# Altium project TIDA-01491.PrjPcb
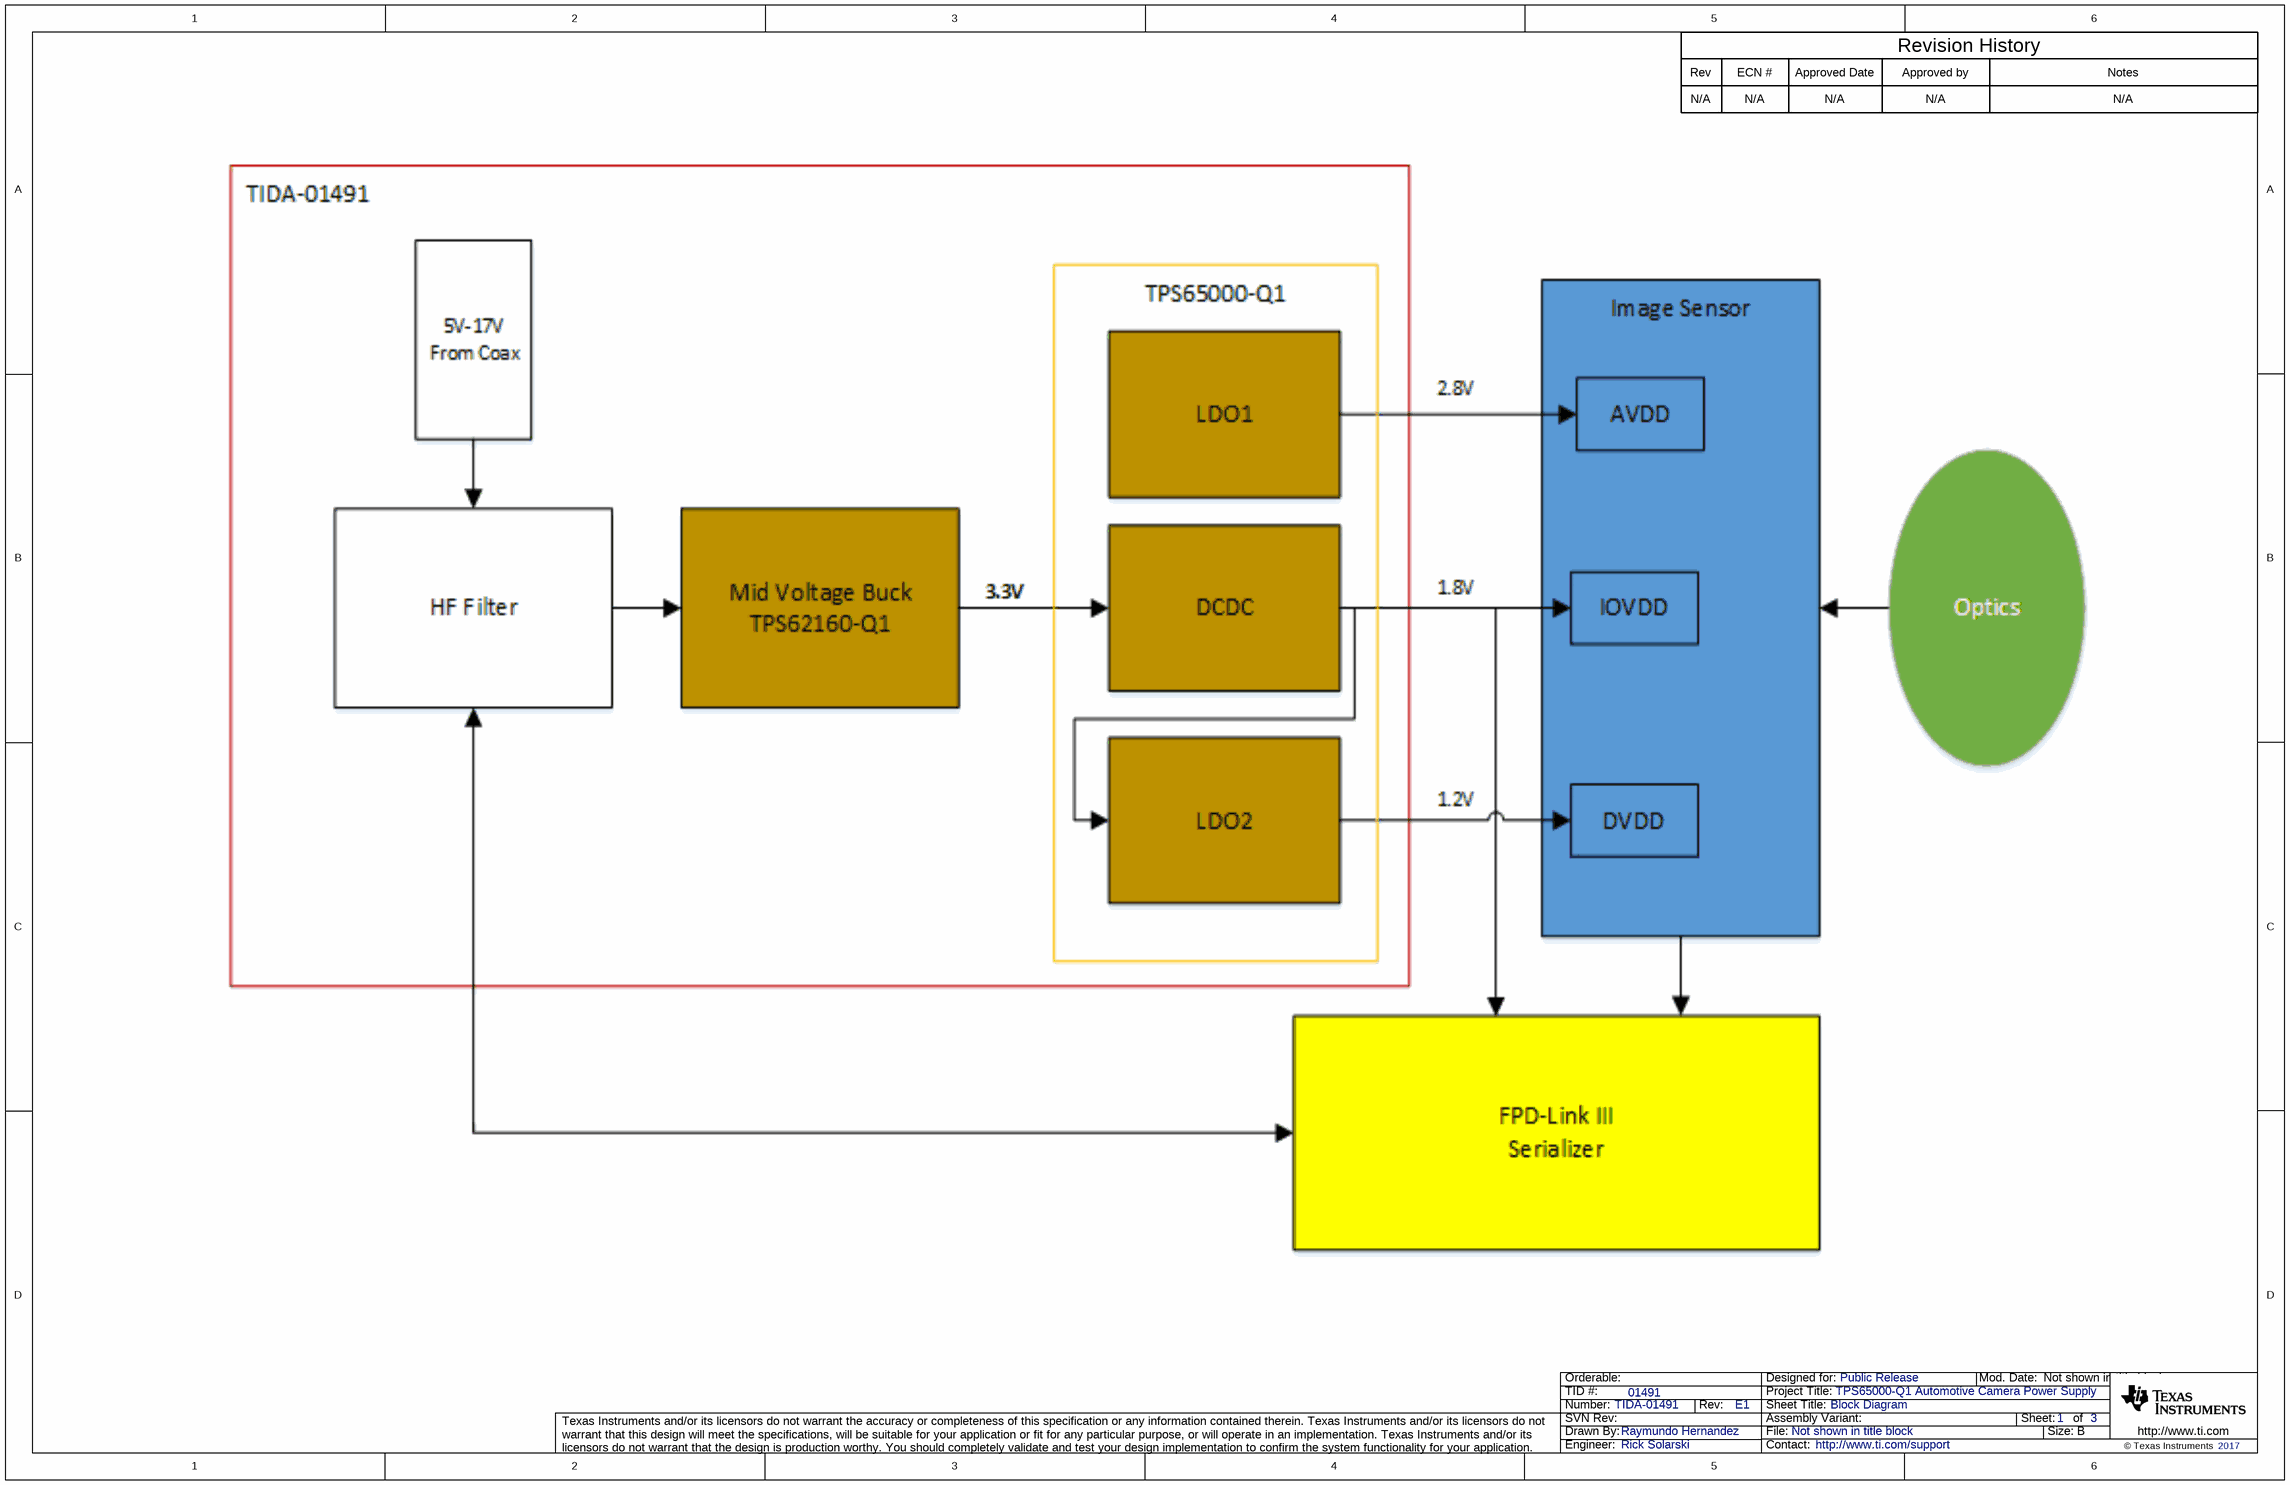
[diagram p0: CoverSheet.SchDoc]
CopyrightYear: 2017; PCB_Layout: Gordon Varney; PCB_Rev: 001; PRJ_Customer: Public Release; PRJ_Engineer: Rick Solarski; PRJ_Number: TIDA-01491; PRJ_Title: TPS65000-Q1 Automotive Camera Power Supply; SCH_Rev: E1; TechSupport: http://www.ti.com/support; TID: 01491
3 sheets, 73 parts. Net scope: global (net labels, ports and power ports of the same name join across sheets).
Board file: TIDA-01491.PcbDoc
Sheets:
  CoverSheet.SchDoc
  TIDA-01491.SchDoc
  EVM_Hardware.SchDoc

## Sheet CoverSheet.SchDoc: Block Diagram
size 431 x 279 mm; Date: Not shown in title block; ApprovedBy: Not shown in title block; CheckedBy: Not shown in title block; Author: Not shown in title block; CompanyName: Not shown in title block; DrawnBy: Raymundo Hernandez; Engineer: Not shown in title block; Organization: Not shown in title block; Address1: Not shown in title block; Address2: Not shown in title block; Address3: Not shown in title block; Address4: Not shown in title block; DocumentNumber: 1; Revision: Use project parameter SCH_Rev; SheetNumber: 1; SheetTotal: 3; PageSetup: Record=PageOptions¦CenterHorizontal=True¦CenterVertical=True¦PrintScale=1.00¦XCorrection=1.00¦YCorrection=1.00¦PrintKind=0¦BorderSize=5000000¦LeftOffset=0¦BottomOffset=0¦Orientation=2¦PaperLength=1000¦PaperWidth=1000¦Scale=100¦PaperSource=15¦PrintQuality=600¦MediaType=1¦DitherType=10¦PaperKind=Letter¦PrintScaleMode=1

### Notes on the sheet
- Rev
- N/A
- ECN #
- Approved Date
- Approved by
- Revision History
- Notes

## Sheet TIDA-01491.SchDoc: Schematic Automotive Camera Power Supply
size 431 x 279 mm; Date: Not shown in title block; ApprovedBy: Not shown in title block; CheckedBy: Not shown in title block; Author: Not shown in title block; CompanyName: Not shown in title block; DrawnBy: Rick Solarski; Engineer: Not shown in title block; Organization: Not shown in title block; Address1: Not shown in title block; Address2: Not shown in title block; Address3: Not shown in title block; Address4: Not shown in title block; DocumentNumber: 1; Revision: Use project parameter SCH_Rev; SheetNumber: 2; SheetTotal: 3; PageSetup: Record=PageOptions¦CenterHorizontal=True¦CenterVertical=True¦PrintScale=0.62¦XCorrection=1.00¦YCorrection=1.00¦PrintKind=0¦BorderSize=5000000¦LeftOffset=0¦BottomOffset=0¦Orientation=2¦PaperLength=1000¦PaperWidth=1000¦Scale=100¦PaperSource=15¦PrintQuality=-3¦MediaType=1¦DitherType=10¦PrintScaleMode=1¦PaperKind=Letter¦PaperIndex=1
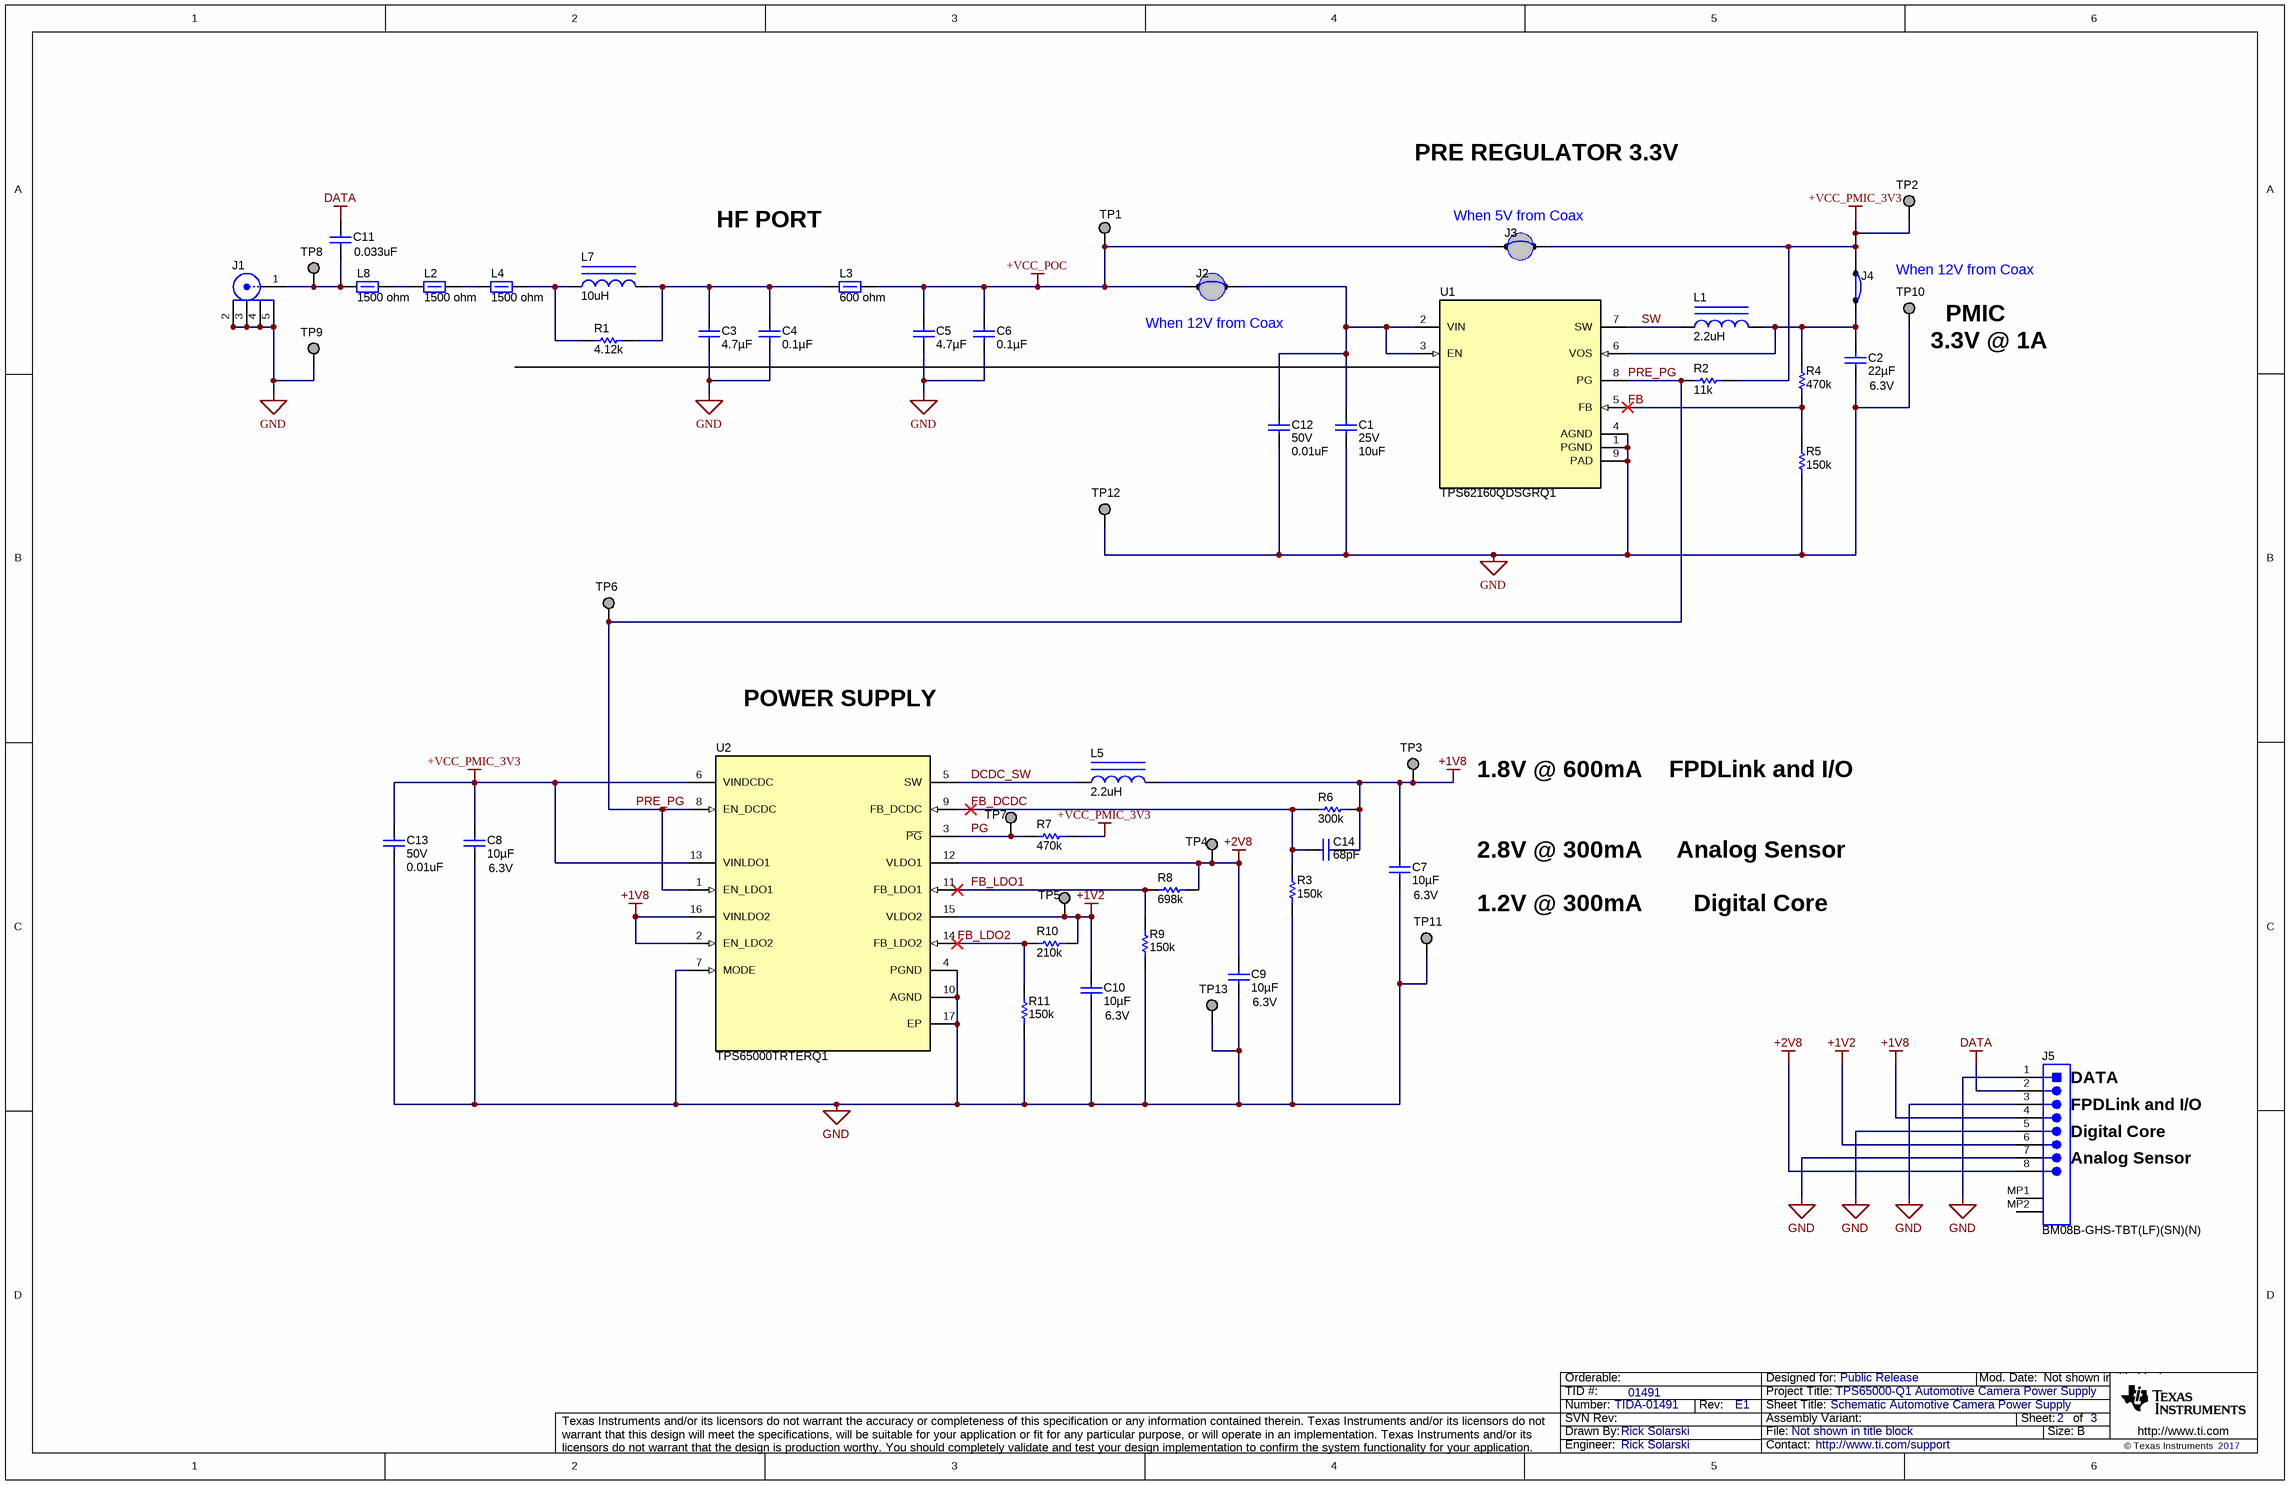
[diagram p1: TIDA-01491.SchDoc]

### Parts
C1  VDC_V: 25V  ValueDisplayed: 10uF  [1206_190L]  (hidden comment: GCM31CC71E106KA03L)
C2  ValueDisplayed: 22µF  Value2: 6.3V  [1206_180L]  (hidden comment: GCM31CR70J226KE23L)
C3  ValueDisplayed: 4.7µF  [0805L]  (hidden comment: GCM21BC71E475KE36L)
C4  ValueDisplayed: 0.1µF  [0603L]  (hidden comment: CGA3E2X7R1E104K080AA)
C5  ValueDisplayed: 4.7µF  [0805L]  (hidden comment: GCM21BC71E475KE36L)
C6  ValueDisplayed: 0.1µF  [0603L]  (hidden comment: CGA3E2X7R1E104K080AA)
C7  ValueDisplayed: 10µF  Value2: 6.3V  [0805L]  (hidden comment: GCM21BR70J106KE22L)
C8  ValueDisplayed: 10µF  Value2: 6.3V  [0805L]  (hidden comment: GCM21BR70J106KE22L)
C9  ValueDisplayed: 10µF  Value2: 6.3V  [0805L]  (hidden comment: GCM21BR70J106KE22L)
C10  ValueDisplayed: 10µF  Value2: 6.3V  [0805L]  (hidden comment: GCM21BR70J106KE22L)
C11  ValueDisplayed: 0.033uF  [0402L]  (hidden comment: CGA2B1X7R1E333K050BC)
C12  VDC_V: 50V  ValueDisplayed: 0.01uF  [0402]  (hidden comment: CGA2B3X7R1H103K050BB)
C13  VDC_V: 50V  ValueDisplayed: 0.01uF  [0402]  (hidden comment: CGA2B3X7R1H103K050BB)
C14  ValueDisplayed: 68pF  [0603L]  (hidden comment: GCM1885C1H680JA16D)
J1  59S10H-40ML5-Z  [Rosenberger_59S10H-40ML5-Z]  (value not drawn)
J2  JMP-36-30X40SMT  [JMP-36-30X40SMT]  (value not drawn)
J3  JMP-36-30X40SMT  [JMP-36-30X40SMT]  (value not drawn)
J4  JMP-36-30X40SMT  [JMP-36-30X40SMT]  (value not drawn)
J5  BM08B-GHS-TBT(LF)(SN)(N)  [JST_BM08B-GHS-TBT]
L1  ValueDisplayed: 2.2uH  [SRN2010TA]  (hidden comment: SRN2010TA-2R2M)
L2  ValueDisplayed: 1500 ohm  [0603L]  (hidden comment: BLM18HE152SN1D)
L3  ValueDisplayed: 600 ohm  [0603L]  (hidden comment: BLM18KG601SN1D)
L4  ValueDisplayed: 1500 ohm  [0603L]  (hidden comment: BLM18HE152SN1D)
L5  ValueDisplayed: 2.2uH  [SRN2010TA]  (hidden comment: SRN2010TA-2R2M)
L7  ValueDisplayed: 10uH  [LQH3NPZ_JR]  (hidden comment: LQH3NPZ100MJRL)
L8  ValueDisplayed: 1500 ohm  [0603L]  (hidden comment: BLM18HE152SN1D)
R1  ValueDisplayed: 4.12k  [0603]  (hidden comment: ERA-3AEB4121V)
R2  ValueDisplayed: 11k  [0402L]  (hidden comment: CRCW040211K0JNED)
R3  ValueDisplayed: 150k  [0402L]  (hidden comment: ERJ-2RKF1503X)
R4  ValueDisplayed: 470k  [0402L]  (hidden comment: ERJ-2RKF4703X)
R5  ValueDisplayed: 150k  [0402L]  (hidden comment: ERJ-2RKF1503X)
R6  ValueDisplayed: 300k  [0402L]  (hidden comment: CRCW0402300KFKED)
R7  ValueDisplayed: 470k  [0402L]  (hidden comment: ERJ-2RKF4703X)
R8  ValueDisplayed: 698k  [0402L]  (hidden comment: ERJ-2RKF6983X)
R9  ValueDisplayed: 150k  [0402L]  (hidden comment: ERJ-2RKF1503X)
R10  ValueDisplayed: 210k  [0402L]  (hidden comment: ERJ-2RKF2103X)
R11  ValueDisplayed: 150k  [0402L]  (hidden comment: ERJ-2RKF1503X)
TP1  TP_SM_1MM  [TP_SM_1MM]  (value not drawn)  (no BOM)
TP2  TP_SM_1MM  [TP_SM_1MM]  (value not drawn)  (no BOM)
TP3  TP_SM_1MM  [TP_SM_1MM]  (value not drawn)  (no BOM)
TP4  TP_SM_1MM  [TP_SM_1MM]  (value not drawn)  (no BOM)
TP5  TP_SM_1MM  [TP_SM_1MM]  (value not drawn)  (no BOM)
TP6  TP_SM_1MM  [TP_SM_1MM]  (value not drawn)  (no BOM)
TP7  TP_SM_1MM  [TP_SM_1MM]  (value not drawn)  (no BOM)
TP8  TP_SM_1MM  [TP_SM_1MM]  (value not drawn)  (no BOM)
TP9  TP_SM_1MM  [TP_SM_1MM]  (value not drawn)  (no BOM)
TP10  TP_SM_1MM  [TP_SM_1MM]  (value not drawn)  (no BOM)
TP11  TP_SM_1MM  [TP_SM_1MM]  (value not drawn)  (no BOM)
TP12  TP_SM_1MM  [TP_SM_1MM]  (value not drawn)  (no BOM)
TP13  TP_SM_1MM  [TP_SM_1MM]  (value not drawn)  (no BOM)
U1  TPS62160QDSGRQ1  [DSG0008A]
U2  TPS65000TRTERQ1  [RTE0016C]

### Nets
+1V2: C10.1 J5.6 R10.2 TP5.1 U2.15(VLDO2)
+1V8: C7.1 C14.1 J5.4 L5.2 R6.2 TP3.1 U2.2(EN_LDO2) U2.16(VINLDO2)
+2V8: C9.1 J5.8 R8.2 TP4.1 U2.12(VLDO1)
+VCC_PMIC_3V3: C8.1 C13.1 J3.2 J4.1 R2.2 R7.2 TP2.1 U2.6(VINDCDC) U2.13(VINLDO1)
+VCC_POC: C5.1 C6.1 J2.1 J3.1 L3.2 TP1.1
DATA: C11.1 J5.2
GND: C1.2 C2.2 C3.2 C4.2 C5.2 C6.2 C7.2 C8.2 C9.2 C10.2 C12.2 C13.2 J1.2 J1.3 J1.4 J1.5 J5.1 J5.3 J5.5 J5.7 R3.1 R5.1 R9.1 R11.1 TP9.1 TP10.1 TP11.1 TP12.1 TP13.1 U1.1(PGND) U1.4(AGND) U1.9(PAD) U2.4(PGND) U2.7(MODE) U2.10(AGND) U2.17(EP)
DCDC_SW: L5.1 U2.5(SW)
FB: R4.1 R5.2 U1.5(FB)
FB_DCDC: C14.2 R3.2 R6.1 U2.9(FB_DCDC)
FB_LDO1: R8.1 R9.2 U2.11(FB_LDO1)
FB_LDO2: R10.1 R11.2 U2.14(FB_LDO2)
PG: R7.1 TP7.1 U2.3(~{PG})
PRE_PG: R2.1 TP6.1 U1.8(PG) U2.1(EN_LDO1) U2.8(EN_DCDC)
SW: L1.1 U1.7(SW)
NetC1_1: C1.1 C12.1 J2.2 U1.2(VIN) U1.3(EN)
NetC2_1: C2.1 J4.2 L1.2 R4.2 U1.6(VOS)
NetC3_1: C3.1 C4.1 L3.1 L7.2 R1.2
NetC11_2: C11.2 J1.1 L8.1 TP8.1
NetL2_1: L2.1 L8.2
NetL2_2: L2.2 L4.1
NetL4_2: L4.2 L7.1 R1.1

Not connected (* = marked no-connect by the designer): J5 MP1 MP2

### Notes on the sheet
- PRE REGULATOR 3.3V
- HF PORT
- (near J3) When 5V from Coax
- (near J2) When 12V from Coax
- (near TP10) When 12V from Coax
- (near TP10) PMIC
- (near TP10) 3.3V @ 1A
- POWER SUPPLY
- 1.8V @ 600mA
- FPDLink and I/O
- 2.8V @ 300mA
- 1.2V @ 300mA
- Analog Sensor
- Digital Core
- (near J5) FPDLink and I/O
- (near J5) DATA
- (near J5) Analog Sensor
- (near J5) Digital Core

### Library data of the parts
C1 = CMP-0008807-2: CAP, CERM, 10 uF, 25 V, +/- 10%, X7S, AEC-Q200 Grade 1, 1206_190; Manufacturer: MuRata; TaMin_C: -55°C; Polarized: N; SizeAreaWB_mm2: 10.92; Value1: Unknown; U/M: EA; Value: 10uF; TaMax_C: 125°C; SizeZ_mm: 1.9; SizeX_mm: 3.2; SizeY_mm: 1.6; Cap_Case: 1206; SizeArea_mm2: 5.12; CompType: Capacitor; AEC Qualified: Y; Cap_F: 10µF; AEC Grade: 1; AEC Category: Q200
C2 = GCM31CR70J226KE23L: CAP, CERM, 22 µF, 6.3 V,+/- 10%, X7R, AEC-Q200 Grade 1, 1206; Manufacturer: MuRata; Polarized: N; CompType: Capacitor; Value: 22uF; U/M: EA; Cap_F: 0.000022; Tolerance_%: 10; VDC_V: 6.3; TaMin_C: -55; TaMax_C: 125; Cap_Case: 1206; SizeArea_mm2: 5.12; SizeAreaWB_mm2: 10.92; SizeX_mm: 3.2; SizeY_mm: 1.6; SizeZ_mm: 1.8; AEC Category: Q200; AEC Qualified: Y; AEC Grade: 1
C3 C5 = GCM21BC71E475KE36L: CAP, CERM, 4.7 µF, 25 V,+/- 10%, X7S, AEC-Q200 Grade 1, 0805; Manufacturer: MuRata; Value: 4.7uF; VDC_V: 25; Tolerance_%: 10; Polarized: N; CompType: Capacitor; U/M: EA; Cap_F: 0.0000047; Value2: 25V; TaMin_C: -55; TaMax_C: 125; Cap_Case: 0805; SizeArea_mm2: 2.5; SizeAreaWB_mm2: 6.75; SizeX_mm: 2; SizeY_mm: 1.25; SizeZ_mm: 1.45; AEC Category: Q200; AEC Qualified: Y; AEC Grade: 1
C4 C6 = CGA3E2X7R1E104K080AA: CAP, CERM, 0.1 µF, 25 V,+/- 10%, X7R, AEC-Q200 Grade 1, 0603; Manufacturer: TDK; Value: 0.1uF; VDC_V: 25; Tolerance_%: 10; Polarized: N; CompType: Capacitor; U/M: EA; Cap_F: 0.0000001; Value2: 25V; TaMin_C: -55; TaMax_C: 125; Cap_Case: 0603; SizeArea_mm2: 1.28; SizeAreaWB_mm2: 4.68; SizeX_mm: 1.6; SizeY_mm: 0.8; SizeZ_mm: 1; AEC Category: Q200; AEC Qualified: Y
C7-C10 = GCM21BR70J106KE22L: CAP, CERM, 10 µF, 6.3 V,+/- 10%, X7R, AEC-Q200 Grade 1, 0805; Manufacturer: MuRata; Polarized: N; CompType: Capacitor; Value: 10uF; U/M: EA; Cap_F: 0.00001; Tolerance_%: 10; VDC_V: 6.3; TaMin_C: -55; TaMax_C: 125; Cap_Case: 0805; SizeArea_mm2: 2.5; SizeAreaWB_mm2: 6.75; SizeX_mm: 2; SizeY_mm: 1.25; SizeZ_mm: 1.45; AEC Category: Q200; AEC Qualified: Y; AEC Grade: 1; Green_Lifecycle: Active; Green_REACh: Passed
C11 = CMP-0006306-2: CAP, CERM, 0.033 uF, 25 V, +/- 10%, X7R, AEC-Q200 Grade 1, 0402; Manufacturer: TDK; TaMin_C: -55°C; Polarized: N; SizeAreaWB_mm2: 3; Value1: Unknown; U/M: EA; TaMax_C: 125°C; SizeZ_mm: 0.6; SizeX_mm: 1; SizeY_mm: 0.5; Cap_Case: 0402; Value2: 25V; CompType: Capacitor; AEC Qualified: Y; Cap_F: 33nF; AEC Category: Q200
C12 C13 = CMP-0006324-2: CAP, CERM, 0.01 uF, 50 V, +/- 10%, X7R, AEC-Q200 Grade 1, 0402; Manufacturer: TDK; TaMin_C: -55°C; ESR_ohm: 3.33065d; Polarized: N; SizeAreaWB_mm2: 3; Value1: 0.333065 ohm; U/M: EA; Value: 0.01uF; TaMax_C: 125°C; SizeZ_mm: 0.6; SizeX_mm: 1; SizeY_mm: 0.5; AEC Qualified: Y; Cap_F: 10nF; IRMS_A: 3.23373dA; AEC Category: Q200
C14 = CMP-0007129-4: CAP, CERM, 68 pF, 50 V, +/- 5%, C0G/NP0, AEC-Q200 Grade 1, 0603; Manufacturer: MuRata; TaMin_C: -55°C; Polarized: N; SizeAreaWB_mm2: 4.68; Value1: Unknown; U/M: EA; Value: 68pF; TaMax_C: 125°C; SizeZ_mm: 1; SizeX_mm: 1.6; SizeY_mm: 0.8; Cap_Case: 0603; Value2: 50V; SizeArea_mm2: 1.28; CompType: Capacitor; AEC Qualified: Y; AEC Category: Q200
J1 = CMP-0075127-1: Connector, HF, 50 Ohm, TH; Manufacturer: Rosenberger; CNHeader: False; Green_Lifecycle: Not Set; Gender: Male; Green_REACh: Incomplete; ContactFinish: Gold
J2-J4 = CMP-0003883-1: Jumper, SMT; Manufacturer: Any
J5 = CMP-0078455-1: Header(shrouded), 1.25mm, 8x1, Tin, TH; Manufacturer: JST Manufacturing; Pitch_mm: 1.25; Gender: Male; Cert_UL: Y; Voltage_V: 50V; Current_A: 1A; Row_Count: 1
L1 L5 = CMP-0056730-1: Inductor, Shielded, Ferrite, 2.2 uH, 1.2 A, 0.174 ohm, AEC-Q200 Grade 1, SMD; Manufacturer: Bourns; Isat: 1.26A @ 30% inductance drop; Irms: 1.2A @ 40C rise; Green_Lifecycle: Active; SizeAreaWB_mm2: 7.8; DCR_ohm: 1.74d; Green_REACh: Passed; Value: 2.2uH; Imax_A: 1.2A; SizeZ_mm: 1; SizeX_mm: 2; SizeY_mm: 1.6; SizeArea_mm2: 3.2; Ind_H: 2.2µH; AEC Qualified: Y; AEC Category: Q200
L2 L4 L8 = BLM18HE152SN1D: Ferrite Bead, 1500 ohm @ 100 MHz, 0.5 A, 0603; Manufacturer: MuRata; Imax_A: 0.5; Value1: 0.5 ohm; Value2: 0.5A; SizeAreaWB_mm2: 4.68; SizeArea_mm2: 1.28; SizeX_mm: 1.6; SizeY_mm: 0.8; SizeZ_mm: 1; ZTyp@100MHz_Ohm: 1500; Green_Lifecycle: Active; Green_REACh: Passed
L3 = BLM18KG601SN1D: Ferrite Bead, 600 ohm @ 100 MHz, 1.3 A, 0603; Manufacturer: MuRata; Value: 600 ohm; Imax_A: 1.3; DCR_ohm: 0.15; Value1: 0.15 ohm; Value2: 1.3A; SizeAreaWB_mm2: 4.68; SizeArea_mm2: 1.28; SizeX_mm: 1.6; SizeY_mm: 0.8; SizeZ_mm: 1; ZTyp@100MHz_Ohm: 600; Green_Lifecycle: Active; Green_REACh: Passed
L7 = CMP-0058702-1: Inductor, Wirewound, Ferrite, 10 uH, 0.81 A, 0.288 ohm, AEC-Q200 Grade 1, SMD; Manufacturer: MuRata; Isat: 0.81A @ 30% inductance drop; Irms: 1.2A @ 40C rise; SizeAreaWB_mm2: 16; DCR_ohm: 2.88d; Value: 10uH; Imax_A: 8.1dA; SizeZ_mm: 1.2; SizeX_mm: 3; Value2: 0.81A; SizeArea_mm2: 9; Ind_H: 10µH; AEC Qualified: Y; AEC Grade: 1; AEC Category: Q200
R1 = CMP-0023378-3: RES, 4.12 k, 0.1%, 0.1 W, AEC-Q200 Grade 0, 0603; Manufacturer: Panasonic; Power_W: 100mW; TempCo: 25 ppm/C; Value_Code: 4k12; U/M: EA; Value: 4.12k; EIA_Code: E192; SizeX_mm: 1.6; SizeY_mm: 0.8; SizeZ_mm: 1; Value2: 0.1W; SizeArea_mm2: 1.28; AEC Qualified: Y; VDC_V: 75V; AEC Grade: 0; AEC Category: Q200
R2 = CMP-0026830-3: RES, 11 k, 5%, 0.063 W, AEC-Q200 Grade 0, 0402; Manufacturer: Vishay-Dale; Power_W: 63mW; TempCo: 200 ppm/C; Value_Code: 11k0; Value: 11k; EIA_Code: E24; SizeX_mm: 1; SizeY_mm: 0.5; SizeZ_mm: 0.6; Value2: 0.063W; CompType: Resistor; AEC Qualified: Y; VDC_V: 50V; AEC Grade: 0; AEC Category: Q200
R3 R5 R11 = CMP-0026669-1: RES, 150 k, 1%, 0.1 W, AEC-Q200 Grade 0, 0402; Manufacturer: Panasonic; Power_W: 100mW; TempCo: 100 ppm/C; U/M: EA; Value: 150k; EIA_Code: E96; SizeX_mm: 1; SizeY_mm: 0.5; SizeZ_mm: 0.6; Value2: 0.1W; CompType: Resistor; AEC Qualified: Y; VDC_V: 50V; AEC Grade: 0; AEC Category: Q200
R4 R7 = CMP-0078374-1: RES, 470 k, 1%, .1 W, AEC-Q200 Grade 0, 0402; Manufacturer: Panasonic; CompType: Resistor; Value: 470k; Res_ohm: 470000; Tolerance_%: 1; Power_W: 0.1; Value2: .1W; VDC_V: 50; TempCo: 100 ppm/C; SizeArea_mm2: 0.5; SizeZ_mm: 0.6; AEC Category: Q200; AEC Qualified: Y; AEC Grade: 0
R6 = CRCW0402300KFKED: RES, 300 k, 1%, 0.063 W, AEC-Q200 Grade 0, 0402; Manufacturer: Vishay-Dale; CompType: Resistor; Value: 300k; Res_ohm: 300000; Tolerance_%: 1; Power_W: 0.063; Value2: 0.063W; VDC_V: 50; TempCo: 100 ppm/C; SizeArea_mm2: 0.5; SizeZ_mm: 0.6; U/M: EA; AEC Category: Q200; AEC Qualified: Y; AEC Grade: 0
R8 = CMP-0078375-1: RES, 698 k, 1%, .1 W, AEC-Q200 Grade 0, 0402; Manufacturer: Panasonic; CompType: Resistor; Value: 698k; Res_ohm: 698000; Tolerance_%: 1; Power_W: 0.1; Value2: .1W; VDC_V: 50; TempCo: 100 ppm/C; SizeArea_mm2: 0.5; SizeZ_mm: 0.6; EIA_Code: E96; AEC Category: Q200; AEC Qualified: Y; AEC Grade: 0
R9 = CMP-0026669-1: RES, 150 k, 1%, 0.1 W, AEC-Q200 Grade 0, 0402; Manufacturer: Panasonic; Power_W: 100mW; TempCo: 100 ppm/C; U/M: EA; Value: 150k; EIA_Code: E96; SizeX_mm: 1; SizeY_mm: 0.5; SizeZ_mm: 0.6; Value2: 0.1W; AEC Qualified: Y; VDC_V: 50V; AEC Grade: 0; AEC Category: Q200
R10 = CMP-0026678-1: RES, 210 k, 1%, 0.1 W, AEC-Q200 Grade 0, 0402; Manufacturer: Panasonic; Power_W: 100mW; TempCo: 100 ppm/C; U/M: EA; Value: 210k; EIA_Code: E96; SizeX_mm: 1; SizeY_mm: 0.5; SizeZ_mm: 0.6; Value2: 0.1W; CompType: Resistor; AEC Qualified: Y; VDC_V: 50V; AEC Grade: 0; AEC Category: Q200
TP1-TP13 = CMP-0003825-1: 1mm Test Point, SMT; Manufacturer: Any
U1 = TPS62160QDSGRQ1: 3V-17V 1A Automotive Step-Down Converters in 2x2SON, DSG0008A (WSON-8); Alternate PartNumber: TPS62160QDSGTQ1; Manufacturer: Texas Instruments; SymbolCreator: Altium; SizeArea_mm2: 4; SizeAreaWB_mm2: 9; SizeX_mm: 2; SizeZ_mm: 0.8; CompType: IC; U/M: EA
U2 = TPS65000TRTERQ1: 2.25MHz Step-Down Converter with Dual LDOs & SVS Power Management IC (PMIC), RTE0016C (WQFN-16); Manufacturer: Texas Instruments; SymbolCreator: Altium; SizeArea_mm2: 9; SizeAreaWB_mm2: 16; SizeX_mm: 3; SizeZ_mm: 0.8; U/M: EA

## Sheet EVM_Hardware.SchDoc: Hardware
size 431 x 279 mm; Date: Not shown in title block; ApprovedBy: Not shown in title block; CheckedBy: Not shown in title block; Author: Not shown in title block; CompanyName: Not shown in title block; DrawnBy: Gordon Varney; Engineer: Not shown in title block; Organization: Not shown in title block; Address1: Not shown in title block; Address2: Not shown in title block; Address3: Not shown in title block; Address4: Not shown in title block; DocumentNumber: 1; Revision: Use project parameter SCH_Rev; SheetNumber: 3; SheetTotal: 3; PageSetup: Record=PageOptions¦CenterHorizontal=True¦CenterVertical=True¦PrintScale=1.00¦XCorrection=1.00¦YCorrection=1.00¦PrintKind=0¦BorderSize=5000000¦LeftOffset=0¦BottomOffset=0¦Orientation=2¦PaperLength=1000¦PaperWidth=1000¦Scale=100¦PaperSource=15¦PrintQuality=600¦MediaType=1¦DitherType=10¦PaperKind=Letter¦PrintScaleMode=1
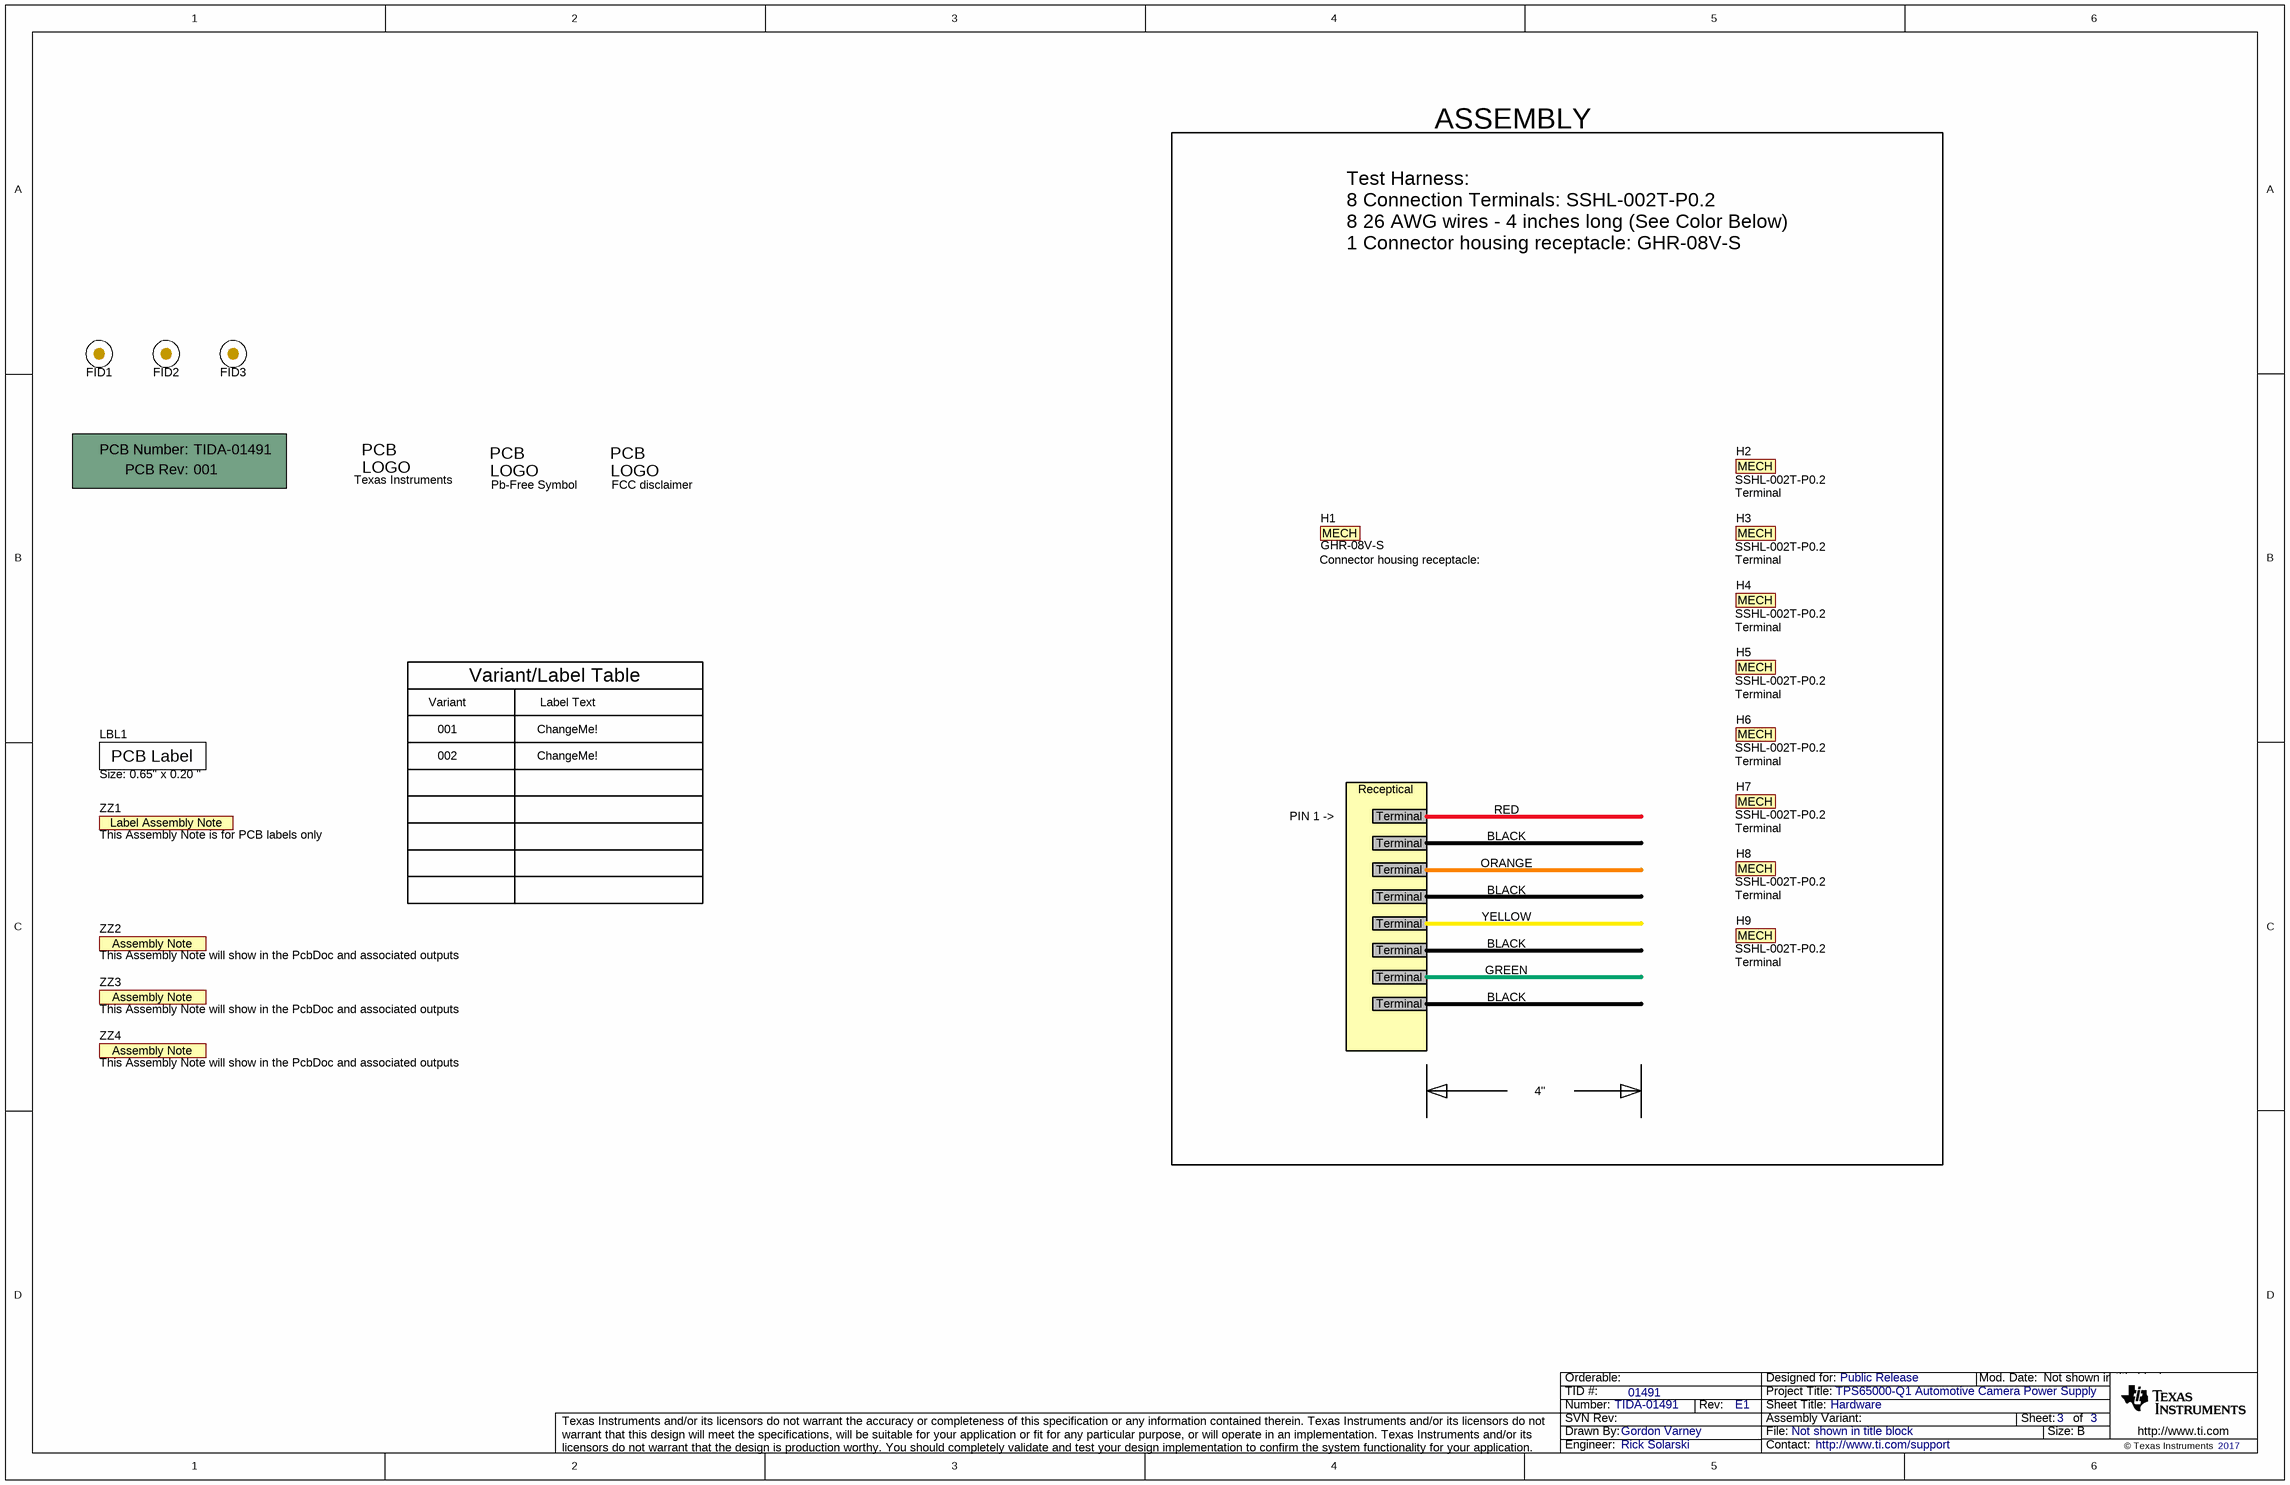
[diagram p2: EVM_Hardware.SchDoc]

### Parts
!PCB1  Printed Circuit Board  (value not drawn)  (mechanical)
FID1  Fiducial  [Fiducial6.4-20]  (value not drawn)  (no BOM)
FID2  Fiducial  [Fiducial6.4-20]  (value not drawn)
FID3  Fiducial  [Fiducial6.4-20]  (value not drawn)
H1  GHR-08V-S  CompType: Connector housing receptacle:  (mechanical)
H2  SSHL-002T-P0.2  PackageReference: Terminal  (mechanical)
H3  SSHL-002T-P0.2  PackageReference: Terminal  (mechanical)
H4  SSHL-002T-P0.2  PackageReference: Terminal  (mechanical)
H5  SSHL-002T-P0.2  PackageReference: Terminal  (mechanical)
H6  SSHL-002T-P0.2  PackageReference: Terminal  (mechanical)
H7  SSHL-002T-P0.2  PackageReference: Terminal  (mechanical)
H8  SSHL-002T-P0.2  PackageReference: Terminal  (mechanical)
H9  SSHL-002T-P0.2  PackageReference: Terminal  (mechanical)
LBL1  Size: 0.65" x 0.20 "  [Label_650x200]
Logo1  Pb-Free Symbol  [Pb-Free_Overlay_Small]  (no BOM)
Logo2  FCC disclaimer  [FCC_disclaimer_stacked]  (no BOM)
Logo3  Texas Instruments  [TI_Symbol_Overlay_Small]  (no BOM)
ZZ1  This Assembly Note is for PCB labels only  [AssemblyNoteLabel]  (no BOM)
ZZ2  This Assembly Note will show in the PcbDoc and associated outputs  [AssemblyNote]  (no BOM)
ZZ3  This Assembly Note will show in the PcbDoc and associated outputs  [AssemblyNote]  (no BOM)
ZZ4  This Assembly Note will show in the PcbDoc and associated outputs  [AssemblyNote]  (no BOM)

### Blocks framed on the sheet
ASSEMBLY: H1-H9

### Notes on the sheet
- Test Harness:
  8 Connection Terminals: SSHL-002T-P0.2
  8 26 AWG wires - 4 inches long (See Color Below)
  1 Connector housing receptacle: GHR-08V-S
- Variant
- Variant/Label Table
- Label Text
- 001
- 002
- ChangeMe!
- PIN 1 ->
- Receptical
- Terminal
- RED
- BLACK
- ORANGE
- YELLOW
- GREEN
- 4"

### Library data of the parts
!PCB1 = PCB: Manufacturer: Any; PartNumber: TIDA-01491; SymbolCreator: a0412235
FID1-FID3 = Fiducial: Fiducial mark.  There is nothing to buy or mount.; SymbolCreator: codlsc
H1 = MechPart: Will add component to BOM.  Useful for cables, nuts, etc. not in libraries; Manufacturer: JST; SymbolCreator: codlsc; U/M: EA
H2-H9 = MechPart: Will add component to BOM.  Useful for cables, nuts, etc. not in libraries; Manufacturer: JST; SymbolCreator: codlsc; CompType: Mechanical; U/M: EA
LBL1 = THT-14-423-10: Thermal Transfer Printable Labels, 0.650" W x 0.200" H - 10,000 per roll; Manufacturer: Brady; SymbolCreator: a0412235; CompType: Label; Green_Lifecycle: Not Set; Green_REACh: Incomplete
Logo1 = Pb-Free: SymbolCreator: a0412235
Logo2 = FCC_disclaimer: SymbolCreator: a0412235
Logo3 = TI_Logo: Texas Instrument Corporate Signature; SymbolCreator: a0412235
ZZ1 = AssemblyNoteLabel: SymbolCreator: a0412235
ZZ2-ZZ4 = AssemblyNote: SymbolCreator: codlsc

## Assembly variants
001: not fitted FID1 FID2 FID3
